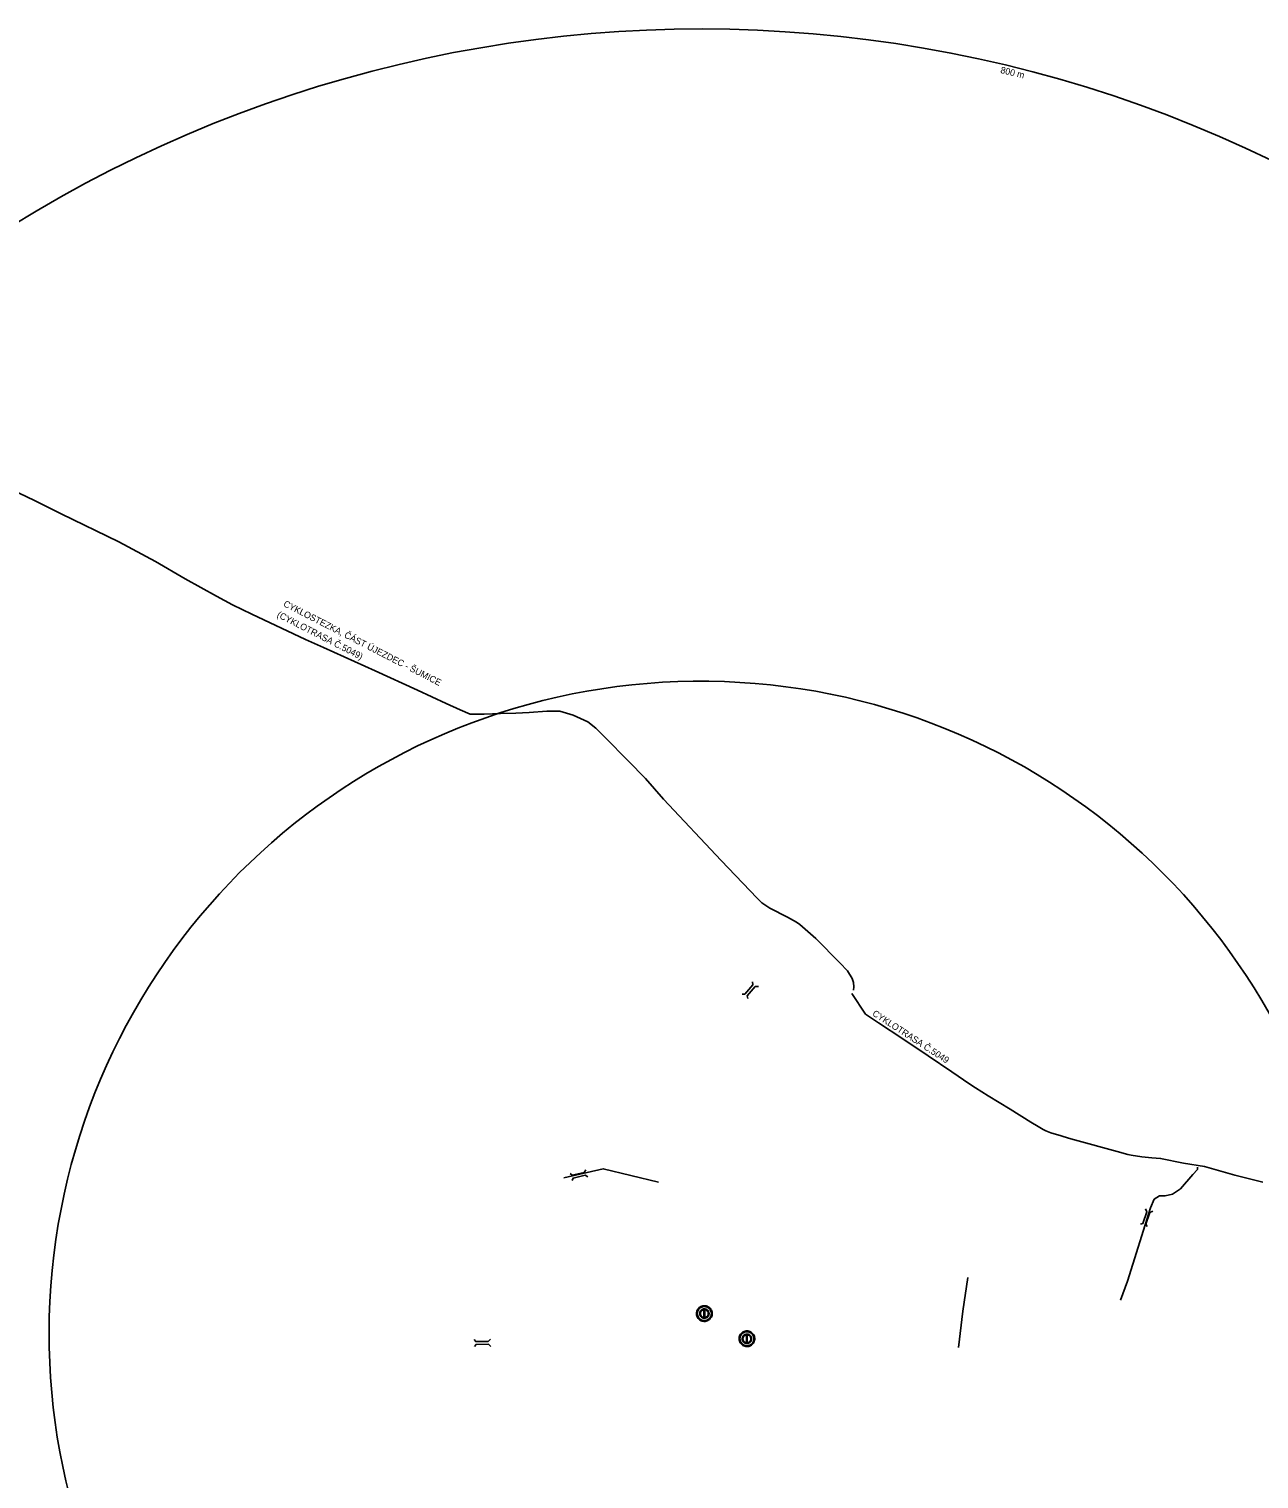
# Model space of a CAD drawing. Extents: x -520790 to -517278, y -1190021 to -1185077.
# Drawn here: x -520310 to -519555, y -1187341 to -1186452 of the extents above; entities that cross this region are included whole.
import ezdxf

# ---------------------------------------------------------------- set-up
doc = ezdxf.new("R2010")
doc.units = 0
for name, color, linetype in [('cyklostezka_s', 7, 'Continuous'), ('dostupnost_s', 7, 'Continuous'), ('most_s', 7, 'Continuous'), ('stezka_s', 7, 'Continuous'), ('zast_HD_s', 7, 'Continuous')]:
    doc.layers.add(name, color=color, linetype=linetype)

msp = doc.modelspace()

# ---------------------------------------------------------------- linework, layer by layer
at = {"layer": 'cyklostezka_s'}
for points in [[(-520320.98, -1186734.51), (-520306.84, -1186741.27), (-520290.46, -1186749.39), (-520255.11, -1186766.55), (-520232.5, -1186778.75), (-520214.33, -1186789.25), (-520195.11, -1186800), (-520185.28, -1186805.26), (-520173.47, -1186811.05), (-520140.56, -1186826.42), (-520129.35, -1186831.4), (-520097.71, -1186845.66), (-520071.83, -1186857.64), (-520054.2, -1186865.75), (-520045.59, -1186869.69), (-520039.49, -1186872.24), (-520030.88, -1186872.25), (-520020.78, -1186871.89), (-520011.44, -1186871.7), (-520003.28, -1186871.25), (-519992.51, -1186870.39), (-519984.36, -1186870.53), (-519976.17, -1186872.82), (-519967.27, -1186877.08), (-519962.31, -1186880.93), (-519956.64, -1186886.57), (-519942.5, -1186900.85), (-519931.83, -1186911.8), (-519920.83, -1186924.46), (-519885.36, -1186961.95), (-519863.39, -1186985.15), (-519860.47, -1186987.91), (-519855.63, -1186991.29), (-519844.68, -1186996.78), (-519839.2, -1186999.9), (-519837.16, -1187001.2), (-519833.86, -1187004.08), (-519827.44, -1187009.84), (-519812.61, -1187024.91), (-519807.97, -1187029.66), (-519805.13, -1187034.38), (-519804.17, -1187036.96), (-519803.98, -1187039.49), (-519804.26, -1187041.49)], [(-519805.21, -1187043.52), (-519796.92, -1187056.27), (-519788.98, -1187061.6), (-519774.04, -1187071.49), (-519758.51, -1187081.76), (-519758.51, -1187081.76), (-519744.01, -1187091.65), (-519732.96, -1187099.17), (-519729.46, -1187101.45), (-519721.61, -1187106.3), (-519708.18, -1187114.56), (-519695.36, -1187122.51), (-519690.98, -1187125.22), (-519687.83, -1187127.1), (-519686.14, -1187127.93), (-519683.09, -1187129.1), (-519676.81, -1187130.87), (-519672.43, -1187132.26), (-519668.67, -1187133.34), (-519642.43, -1187140.52), (-519635.85, -1187142.39), (-519633.93, -1187142.68), (-519627.27, -1187143.75), (-519621.29, -1187144.5), (-519615.85, -1187144.77), (-519601.83, -1187147.62), (-519588.92, -1187149.68), (-519570.33, -1187155.07), (-519553.09, -1187159.37)]]:
    msp.add_lwpolyline(points, dxfattribs=at)
at = {"layer": 'dostupnost_s'}
for radius, start, end in [(800, 53.87232, 292.33077), (400, 5.51814, 340.68496)]:
    msp.add_arc((-519897.81, -1187252.07), radius, start, end, dxfattribs=at)
at = {"layer": 'most_s'}
for points in [[(-519866.15, -1187036.37), (-519866.01, -1187038.31), (-519871, -1187044.09), (-519872.63, -1187043.94)], [(-519862.56, -1187039.24), (-519864.49, -1187039.37), (-519869.51, -1187045.13), (-519869.14, -1187046.72)], [(-519968.46, -1187151.68), (-519969.47, -1187153.33), (-519976.91, -1187155.09), (-519978.14, -1187154.02)], [(-519967.23, -1187156.11), (-519968.87, -1187155.08), (-519976.31, -1187156.81), (-519976.94, -1187158.32)], [(-519625.05, -1187175.7), (-519624.19, -1187177.45), (-519626.68, -1187184.67), (-519628.25, -1187185.14)], [(-519620.64, -1187177.03), (-519622.39, -1187177.87), (-519624.91, -1187185.09), (-519623.98, -1187186.43)], [(-520027.06, -1187255.55), (-520028.41, -1187256.95), (-520036.05, -1187257.07), (-520037.02, -1187255.76)], [(-520026.81, -1187260.14), (-520028.2, -1187258.78), (-520035.83, -1187258.88), (-520036.78, -1187260.21)]]:
    msp.add_lwpolyline(points, dxfattribs=at)
at = {"layer": 'stezka_s'}
for points in [[(-519982.08, -1187156.72), (-519957.77, -1187151.1), (-519923.87, -1187159.26)], [(-519593.09, -1187150.06), (-519593.18, -1187150.9), (-519593.27, -1187151.64), (-519595.96, -1187154.69), (-519603.51, -1187163.32), (-519608.54, -1187166.73), (-519613.03, -1187167.63), (-519616.44, -1187167.81), (-519619.86, -1187169.79), (-519622.01, -1187175), (-519636.21, -1187220.09), (-519640.38, -1187231.66)], [(-519734.03, -1187217.79), (-519737.21, -1187238.49), (-519739.73, -1187260.77)]]:
    msp.add_lwpolyline(points, dxfattribs=at)
at = {"layer": 'zast_HD_s'}
for p, q in [((-519895.51, -1187242.78), (-519895.51, -1187242.78)), ((-519869.4, -1187258.23), (-519869.4, -1187258.23))]:
    msp.add_line(p, q, dxfattribs=at)
for points in [[(-519895.77, -1187235.12), (-519896.17, -1187235.13), (-519896.77, -1187235.22), (-519897.35, -1187235.39), (-519897.91, -1187235.62), (-519898.44, -1187235.93), (-519898.92, -1187236.3), (-519899.35, -1187236.72), (-519899.72, -1187237.2), (-519900.04, -1187237.72), (-519900.28, -1187238.28), (-519900.45, -1187238.86), (-519900.55, -1187239.46), (-519900.56, -1187240.07), (-519900.51, -1187240.67), (-519900.37, -1187241.27), (-519900.17, -1187241.84), (-519899.89, -1187242.38), (-519899.55, -1187242.88), (-519899.14, -1187243.33), (-519898.69, -1187243.73), (-519898.18, -1187244.07), (-519897.64, -1187244.34), (-519897.07, -1187244.54), (-519896.47, -1187244.67), (-519895.87, -1187244.72), (-519895.26, -1187244.7), (-519894.66, -1187244.6), (-519894.08, -1187244.42), (-519893.53, -1187244.17), (-519893.01, -1187243.85), (-519892.53, -1187243.48), (-519892.11, -1187243.04), (-519891.75, -1187242.55), (-519891.45, -1187242.03), (-519891.22, -1187241.46), (-519891.06, -1187240.88), (-519890.97, -1187240.28), (-519890.97, -1187239.67), (-519891.04, -1187239.07), (-519891.18, -1187238.48), (-519891.4, -1187237.91), (-519891.69, -1187237.38), (-519892.04, -1187236.88), (-519892.46, -1187236.44), (-519892.92, -1187236.05), (-519893.43, -1187235.72), (-519893.98, -1187235.46), (-519894.56, -1187235.27), (-519895.16, -1187235.16), (-519895.76, -1187235.12)], [(-519891.44, -1187239.92), (-519891.48, -1187239.37), (-519891.58, -1187238.84), (-519891.75, -1187238.32), (-519891.98, -1187237.82), (-519892.28, -1187237.36), (-519892.63, -1187236.94), (-519893.03, -1187236.57), (-519893.47, -1187236.25), (-519893.95, -1187235.99), (-519894.46, -1187235.8), (-519894.99, -1187235.67), (-519895.54, -1187235.6), (-519896.08, -1187235.61), (-519896.62, -1187235.68), (-519897.15, -1187235.83), (-519897.66, -1187236.03), (-519898.13, -1187236.3), (-519898.57, -1187236.63), (-519898.96, -1187237.01), (-519899.3, -1187237.44), (-519899.59, -1187237.91), (-519899.81, -1187238.4), (-519899.97, -1187238.93), (-519900.06, -1187239.47), (-519900.09, -1187240.01), (-519900.04, -1187240.56), (-519899.93, -1187241.09), (-519899.74, -1187241.61), (-519899.5, -1187242.1), (-519899.2, -1187242.55), (-519898.84, -1187242.96), (-519898.43, -1187243.33), (-519897.98, -1187243.63), (-519897.49, -1187243.88), (-519896.98, -1187244.07), (-519896.44, -1187244.19), (-519895.9, -1187244.24), (-519895.35, -1187244.22), (-519894.81, -1187244.14), (-519894.29, -1187243.98), (-519893.79, -1187243.77), (-519893.32, -1187243.49), (-519892.89, -1187243.15), (-519892.5, -1187242.76), (-519892.17, -1187242.33), (-519891.9, -1187241.85), (-519891.68, -1187241.35), (-519891.54, -1187240.82), (-519891.46, -1187240.28), (-519891.44, -1187239.92)], [(-519895.76, -1187235.6), (-519895.4, -1187235.61), (-519894.86, -1187235.69), (-519894.34, -1187235.84), (-519893.83, -1187236.05), (-519893.36, -1187236.33), (-519892.93, -1187236.66), (-519892.54, -1187237.04), (-519892.2, -1187237.47), (-519891.92, -1187237.94), (-519891.7, -1187238.44), (-519891.55, -1187238.97), (-519891.46, -1187239.51), (-519891.44, -1187240.05), (-519891.49, -1187240.6), (-519891.61, -1187241.13), (-519891.8, -1187241.65), (-519892.05, -1187242.13), (-519892.36, -1187242.58), (-519892.72, -1187242.99), (-519893.13, -1187243.35), (-519893.59, -1187243.66), (-519894.08, -1187243.9), (-519894.59, -1187244.08), (-519895.13, -1187244.2), (-519895.67, -1187244.24), (-519896.22, -1187244.22), (-519896.76, -1187244.13), (-519897.28, -1187243.97), (-519897.78, -1187243.75), (-519898.24, -1187243.46), (-519898.67, -1187243.12), (-519899.05, -1187242.73), (-519899.38, -1187242.29), (-519899.65, -1187241.82), (-519899.86, -1187241.31), (-519900, -1187240.78), (-519900.08, -1187240.24), (-519900.08, -1187239.69), (-519900.02, -1187239.15), (-519899.89, -1187238.62), (-519899.69, -1187238.11), (-519899.43, -1187237.63), (-519899.11, -1187237.19), (-519898.74, -1187236.79), (-519898.32, -1187236.43), (-519897.86, -1187236.14), (-519897.37, -1187235.91), (-519896.85, -1187235.74), (-519896.31, -1187235.63), (-519895.77, -1187235.6)], [(-519896.01, -1187237.06), (-519896.37, -1187237.11), (-519896.72, -1187237.21), (-519897.06, -1187237.35), (-519897.37, -1187237.54), (-519897.66, -1187237.76), (-519897.92, -1187238.01), (-519898.14, -1187238.3), (-519898.32, -1187238.61), (-519898.47, -1187238.95), (-519898.57, -1187239.3), (-519898.63, -1187239.66), (-519898.64, -1187240.02), (-519898.6, -1187240.38), (-519898.52, -1187240.73), (-519898.4, -1187241.08), (-519898.23, -1187241.4), (-519898.02, -1187241.7), (-519897.78, -1187241.97), (-519897.51, -1187242.21), (-519897.2, -1187242.41), (-519896.88, -1187242.57), (-519896.53, -1187242.69), (-519896.18, -1187242.76), (-519895.82, -1187242.79), (-519895.53, -1187242.79)], [(-519895.99, -1187242.32), (-519896.3, -1187242.28), (-519896.59, -1187242.19), (-519896.87, -1187242.07), (-519897.13, -1187241.91), (-519897.37, -1187241.72), (-519897.58, -1187241.51), (-519897.77, -1187241.26), (-519897.92, -1187241), (-519898.04, -1187240.72), (-519898.13, -1187240.42), (-519898.17, -1187240.12), (-519898.18, -1187239.82), (-519898.14, -1187239.51), (-519898.07, -1187239.22), (-519897.97, -1187238.93), (-519897.82, -1187238.66), (-519897.65, -1187238.41), (-519897.44, -1187238.19), (-519897.21, -1187237.99), (-519896.96, -1187237.82), (-519896.68, -1187237.69), (-519896.39, -1187237.59), (-519896.09, -1187237.53), (-519896.01, -1187237.52)], [(-519896.01, -1187237.52), (-519896.01, -1187237.06)], [(-519895.51, -1187242.78), (-519895.16, -1187242.73), (-519894.81, -1187242.63), (-519894.47, -1187242.49), (-519894.16, -1187242.3), (-519893.87, -1187242.08), (-519893.61, -1187241.83), (-519893.39, -1187241.54), (-519893.2, -1187241.23), (-519893.06, -1187240.89), (-519892.96, -1187240.54), (-519892.9, -1187240.19), (-519892.89, -1187239.82), (-519892.93, -1187239.46), (-519893.01, -1187239.11), (-519893.13, -1187238.76), (-519893.3, -1187238.44), (-519893.5, -1187238.14), (-519893.75, -1187237.87), (-519894.02, -1187237.63), (-519894.32, -1187237.43), (-519894.65, -1187237.27), (-519894.99, -1187237.15), (-519895.35, -1187237.08), (-519895.71, -1187237.05), (-519895.99, -1187237.05)], [(-519895.99, -1187237.05), (-519895.99, -1187242.32)], [(-519895.77, -1187235.6), (-519895.77, -1187235.12)], [(-519895.76, -1187235.12), (-519895.76, -1187235.6)], [(-519895.53, -1187242.79), (-519895.53, -1187237.52)], [(-519895.53, -1187237.52), (-519895.23, -1187237.56), (-519894.94, -1187237.65), (-519894.66, -1187237.77), (-519894.4, -1187237.93), (-519894.16, -1187238.12), (-519893.94, -1187238.33), (-519893.76, -1187238.58), (-519893.6, -1187238.84), (-519893.48, -1187239.12), (-519893.4, -1187239.42), (-519893.36, -1187239.72), (-519893.35, -1187240.02), (-519893.38, -1187240.33), (-519893.45, -1187240.62), (-519893.56, -1187240.91), (-519893.7, -1187241.18), (-519893.88, -1187241.43), (-519894.08, -1187241.66), (-519894.32, -1187241.85), (-519894.57, -1187242.02), (-519894.85, -1187242.15), (-519895.14, -1187242.25), (-519895.43, -1187242.31), (-519895.51, -1187242.32)], [(-519895.51, -1187242.32), (-519895.51, -1187242.78)], [(-519869.65, -1187250.57), (-519870.05, -1187250.58), (-519870.65, -1187250.67), (-519871.24, -1187250.83), (-519871.8, -1187251.07), (-519872.32, -1187251.38), (-519872.8, -1187251.75), (-519873.23, -1187252.17), (-519873.61, -1187252.65), (-519873.92, -1187253.17), (-519874.16, -1187253.73), (-519874.33, -1187254.31), (-519874.43, -1187254.91), (-519874.45, -1187255.52), (-519874.39, -1187256.12), (-519874.26, -1187256.71), (-519874.05, -1187257.29), (-519873.78, -1187257.83), (-519873.43, -1187258.33), (-519873.03, -1187258.78), (-519872.57, -1187259.18), (-519872.07, -1187259.52), (-519871.52, -1187259.79), (-519870.95, -1187259.99), (-519870.36, -1187260.12), (-519869.75, -1187260.17), (-519869.15, -1187260.15), (-519868.55, -1187260.04), (-519867.97, -1187259.87), (-519867.41, -1187259.62), (-519866.89, -1187259.3), (-519866.42, -1187258.92), (-519866, -1187258.49), (-519865.63, -1187258), (-519865.33, -1187257.47), (-519865.1, -1187256.91), (-519864.94, -1187256.33), (-519864.86, -1187255.72), (-519864.85, -1187255.12), (-519864.92, -1187254.51), (-519865.07, -1187253.92), (-519865.29, -1187253.36), (-519865.58, -1187252.82), (-519865.93, -1187252.33), (-519866.34, -1187251.89), (-519866.81, -1187251.5), (-519867.32, -1187251.17), (-519867.87, -1187250.91), (-519868.44, -1187250.72), (-519869.04, -1187250.6), (-519869.65, -1187250.57)], [(-519865.33, -1187255.37), (-519865.36, -1187254.82), (-519865.46, -1187254.29), (-519865.63, -1187253.77), (-519865.87, -1187253.27), (-519866.16, -1187252.81), (-519866.51, -1187252.39), (-519866.91, -1187252.02), (-519867.36, -1187251.7), (-519867.84, -1187251.44), (-519868.35, -1187251.25), (-519868.88, -1187251.11), (-519869.42, -1187251.05), (-519869.97, -1187251.06), (-519870.51, -1187251.13), (-519871.04, -1187251.27), (-519871.54, -1187251.48), (-519872.02, -1187251.75), (-519872.46, -1187252.08), (-519872.85, -1187252.46), (-519873.19, -1187252.89), (-519873.47, -1187253.35), (-519873.7, -1187253.85), (-519873.86, -1187254.38), (-519873.95, -1187254.91), (-519873.97, -1187255.46), (-519873.93, -1187256), (-519873.81, -1187256.54), (-519873.63, -1187257.05), (-519873.39, -1187257.54), (-519873.08, -1187258), (-519872.72, -1187258.41), (-519872.31, -1187258.77), (-519871.86, -1187259.08), (-519871.38, -1187259.33), (-519870.86, -1187259.52), (-519870.33, -1187259.64), (-519869.79, -1187259.69), (-519869.24, -1187259.67), (-519868.7, -1187259.59), (-519868.17, -1187259.43), (-519867.67, -1187259.21), (-519867.2, -1187258.93), (-519866.77, -1187258.6), (-519866.39, -1187258.21), (-519866.06, -1187257.77), (-519865.78, -1187257.3), (-519865.57, -1187256.8), (-519865.42, -1187256.27), (-519865.34, -1187255.73), (-519865.33, -1187255.37)], [(-519869.65, -1187251.05), (-519869.29, -1187251.06), (-519868.75, -1187251.14), (-519868.22, -1187251.29), (-519867.72, -1187251.5), (-519867.25, -1187251.78), (-519866.81, -1187252.11), (-519866.42, -1187252.49), (-519866.09, -1187252.92), (-519865.8, -1187253.39), (-519865.59, -1187253.89), (-519865.43, -1187254.42), (-519865.35, -1187254.96), (-519865.33, -1187255.5), (-519865.38, -1187256.05), (-519865.5, -1187256.58), (-519865.69, -1187257.09), (-519865.93, -1187257.58), (-519866.24, -1187258.03), (-519866.61, -1187258.44), (-519867.02, -1187258.8), (-519867.47, -1187259.1), (-519867.96, -1187259.35), (-519868.48, -1187259.53), (-519869.01, -1187259.64), (-519869.56, -1187259.69), (-519870.1, -1187259.67), (-519870.64, -1187259.58), (-519871.16, -1187259.42), (-519871.66, -1187259.19), (-519872.13, -1187258.91), (-519872.56, -1187258.57), (-519872.94, -1187258.18), (-519873.26, -1187257.74), (-519873.53, -1187257.26), (-519873.74, -1187256.76), (-519873.89, -1187256.23), (-519873.96, -1187255.69), (-519873.97, -1187255.14), (-519873.9, -1187254.6), (-519873.77, -1187254.07), (-519873.58, -1187253.56), (-519873.32, -1187253.08), (-519873, -1187252.63), (-519872.63, -1187252.23), (-519872.21, -1187251.88), (-519871.75, -1187251.59), (-519871.25, -1187251.35), (-519870.73, -1187251.18), (-519870.2, -1187251.08), (-519869.65, -1187251.05)], [(-519869.65, -1187250.57), (-519869.65, -1187251.05)], [(-519869.65, -1187251.05), (-519869.65, -1187250.57)], [(-519869.9, -1187252.5), (-519870.26, -1187252.56), (-519870.61, -1187252.66), (-519870.94, -1187252.8), (-519871.26, -1187252.98), (-519871.54, -1187253.21), (-519871.8, -1187253.46), (-519872.02, -1187253.75), (-519872.21, -1187254.06), (-519872.35, -1187254.4), (-519872.46, -1187254.74), (-519872.51, -1187255.1), (-519872.52, -1187255.47), (-519872.49, -1187255.83), (-519872.41, -1187256.18), (-519872.28, -1187256.52), (-519872.11, -1187256.85), (-519871.91, -1187257.15), (-519871.67, -1187257.42), (-519871.39, -1187257.66), (-519871.09, -1187257.86), (-519870.76, -1187258.02), (-519870.42, -1187258.14), (-519870.06, -1187258.21), (-519869.7, -1187258.24), (-519869.42, -1187258.23)], [(-519869.88, -1187257.77), (-519870.18, -1187257.72), (-519870.47, -1187257.64), (-519870.75, -1187257.52), (-519871.02, -1187257.36), (-519871.26, -1187257.17), (-519871.47, -1187256.95), (-519871.66, -1187256.71), (-519871.81, -1187256.45), (-519871.93, -1187256.17), (-519872.01, -1187255.87), (-519872.06, -1187255.57), (-519872.06, -1187255.27), (-519872.03, -1187254.96), (-519871.96, -1187254.66), (-519871.85, -1187254.38), (-519871.71, -1187254.11), (-519871.53, -1187253.86), (-519871.33, -1187253.63), (-519871.1, -1187253.43), (-519870.84, -1187253.27), (-519870.57, -1187253.13), (-519870.28, -1187253.04), (-519869.98, -1187252.98), (-519869.9, -1187252.97)], [(-519869.9, -1187252.97), (-519869.9, -1187252.5)], [(-519869.4, -1187258.23), (-519869.04, -1187258.18), (-519868.69, -1187258.08), (-519868.36, -1187257.94), (-519868.04, -1187257.75), (-519867.75, -1187257.53), (-519867.5, -1187257.27), (-519867.27, -1187256.99), (-519867.09, -1187256.68), (-519866.94, -1187256.34), (-519866.84, -1187255.99), (-519866.79, -1187255.63), (-519866.78, -1187255.27), (-519866.81, -1187254.91), (-519866.89, -1187254.55), (-519867.02, -1187254.21), (-519867.18, -1187253.89), (-519867.39, -1187253.59), (-519867.63, -1187253.32), (-519867.91, -1187253.08), (-519868.21, -1187252.88), (-519868.53, -1187252.72), (-519868.88, -1187252.6), (-519869.23, -1187252.52), (-519869.6, -1187252.49), (-519869.88, -1187252.5)], [(-519869.88, -1187252.5), (-519869.88, -1187257.77)], [(-519869.42, -1187258.23), (-519869.42, -1187252.96)], [(-519869.42, -1187252.96), (-519869.12, -1187253.01), (-519868.82, -1187253.1), (-519868.54, -1187253.22), (-519868.28, -1187253.38), (-519868.04, -1187253.57), (-519867.83, -1187253.78), (-519867.64, -1187254.03), (-519867.49, -1187254.29), (-519867.37, -1187254.57), (-519867.29, -1187254.86), (-519867.24, -1187255.17), (-519867.24, -1187255.47), (-519867.27, -1187255.78), (-519867.34, -1187256.07), (-519867.45, -1187256.36), (-519867.59, -1187256.63), (-519867.76, -1187256.88), (-519867.97, -1187257.1), (-519868.2, -1187257.3), (-519868.46, -1187257.47), (-519868.73, -1187257.6), (-519869.02, -1187257.7), (-519869.32, -1187257.76), (-519869.4, -1187257.77)], [(-519869.4, -1187257.77), (-519869.4, -1187258.23)]]:
    msp.add_lwpolyline(points, dxfattribs=at)

# ---------------------------------------------------------------- texts
at = {"layer": 'cyklostezka_s'}
for s, rotation, p in [('CYKLOSTEZKA, ČÁST ÚJEZDEC - ŠUMICE', 332.85032, (-520154.46, -1186805.87)), ('(CYKLOTRASA Č.5049)', 332.85032, (-520158.4, -1186812.48)), ('CYKLOTRASA Č.5049', 326.85636, (-519793.06, -1187056.8))]:
    msp.add_text(s, height=4, rotation=rotation, dxfattribs=at).set_placement(p)
at = {"layer": 'dostupnost_s'}
msp.add_text('800 m', height=4, rotation=346.42335, dxfattribs=at).set_placement((-519714.36, -1186478.98))

doc.saveas('drawing.dxf')
